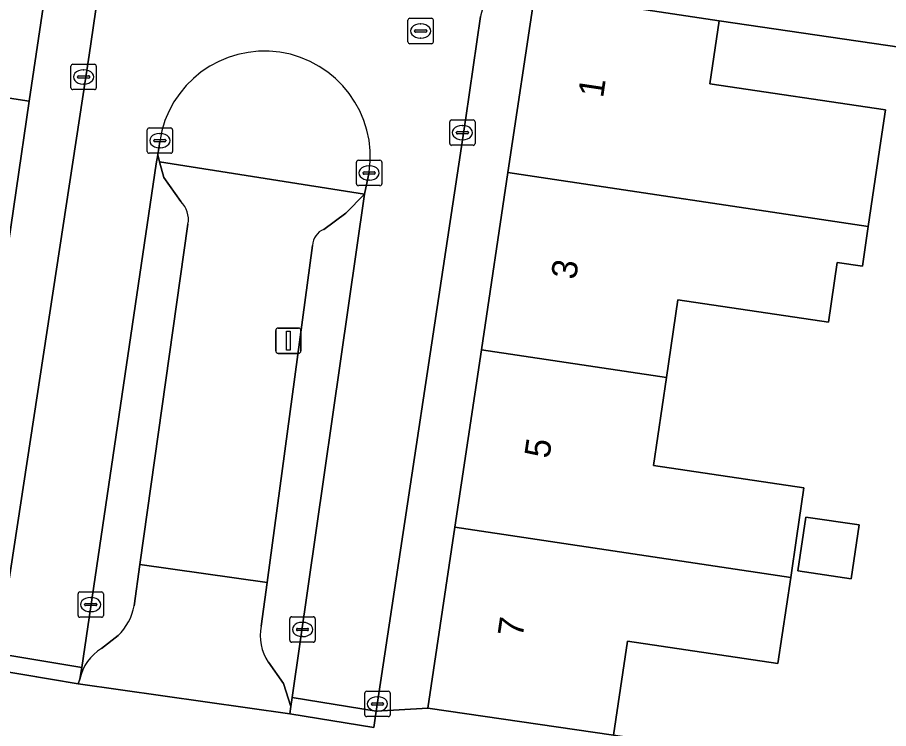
# Model space of a CAD drawing. Extents: x 163683 to 164494, y 382709 to 383872.
# Drawn here: x 164040.44 to 164074.8, y 383054.56 to 383082.57 of the extents above; entities that cross this region are included whole.
import ezdxf

# ---------------------------------------------------------------- set-up
doc = ezdxf.new("R2010")
doc.units = 0
for name, color, linetype in [('IMGEO_Erf', 7, 'Continuous'), ('IMGEO_Groenvoorziening', 7, 'Continuous'), ('IMGEO_Kolk', 7, 'Continuous'), ('IMGEO_Lichtmast', 7, 'Continuous'), ('IMGEO_Pand', 7, 'Continuous'), ('IMGEO_Pand_nummerreeks', 7, 'Continuous'), ('IMGEO_Parkeervlak_open', 7, 'Continuous'), ('IMGEO_Rijbaan_lokaal_open', 7, 'Continuous'), ('IMGEO_Rioolput', 7, 'Continuous'), ('IMGEO_Voetpad_open', 7, 'Continuous')]:
    doc.layers.add(name, color=color, linetype=linetype)

msp = doc.modelspace()

# ---------------------------------------------------------------- linework, layer by layer
at = {"layer": 'IMGEO_Erf'}
for points in [[(164079.081, 383080.842), (164068.118, 383082.441), (164067.751, 383079.962), (164074.676, 383078.936), (164074.495, 383077.716), (164073.995, 383074.34), (164073.762, 383072.77), (164072.773, 383072.917), (164072.426, 383070.573), (164066.489, 383071.452), (164066.035, 383068.386), (164065.522, 383064.923), (164071.458, 383064.044), (164071.165, 383062.066), (164070.935, 383060.513), (164070.432, 383057.12), (164064.496, 383057.999), (164063.947, 383054.299), (164074.971, 383052.645)], [(164073.633, 383062.582), (164073.319, 383060.464), (164071.222, 383060.775), (164071.536, 383062.892)]]:
    msp.add_lwpolyline(points, close=True, dxfattribs=at)
at = {"layer": 'IMGEO_Groenvoorziening'}
for points in [[(164046.054, 383077.691), (164045.976, 383077.163), (164046.049, 383076.883), (164054.125, 383075.618), (164054.32, 383076.482)], [(164052.524, 383074.226), (164053.388, 383074.861), (164054.125, 383075.618), (164046.049, 383076.883), (164046.212, 383076.262), (164046.887, 383075.323)], [(164047.17, 383074.431), (164045.275, 383061.028), (164050.291, 383060.313), (164052.079, 383073.592)], [(164050.06, 383058.594), (164050.291, 383060.313), (164045.275, 383061.028), (164045.045, 383059.399)], [(164044.412, 383058.222), (164043.757, 383057.707)], [(164042.911, 383056.507), (164042.84, 383056.324), (164051.188, 383055.135), (164051.231, 383055.427), (164050.934, 383056.333), (164050.338, 383057.172)]]:
    msp.add_lwpolyline(points, dxfattribs=at)
for centre, radius, start, end in [((164050.185, 383077.072), 4.177, 351.8809, 171.4767), ((164046.184, 383074.609), 1.002, 349.7759, 45.4289), ((164052.784, 383073.57), 0.705, 111.6311, 178.2395), ((164042.941, 383059.772), 2.137, 313.5087, 349.9478), ((164051.895, 383058.215), 1.874, 168.3167, 213.8069), ((164044.665, 383056.169), 1.786, 120.5437, 169.0887)]:
    msp.add_arc(centre, radius, start, end, dxfattribs=at)
at = {"layer": 'IMGEO_Kolk'}
for p, q in [((164042.628, 383080.731), (164043.48, 383080.731)), ((164042.553, 383079.805), (164042.553, 383080.657)), ((164043.041, 383080.511), (164043.066, 383080.511)), ((164043.554, 383080.657), (164043.554, 383079.805)), ((164042.812, 383080.225), (164042.812, 383080.237)), ((164043.25, 383080.188), (164042.852, 383080.188)), ((164042.855, 383080.274), (164043.253, 383080.274)), ((164043.296, 383080.237), (164043.296, 383080.225)), ((164043.48, 383079.731), (164042.628, 383079.731)), ((164043.064, 383079.951), (164043.039, 383079.951)), ((164057.492, 383077.61), (164057.492, 383078.462)), ((164057.567, 383078.536), (164058.419, 383078.536)), ((164058.493, 383078.462), (164058.493, 383077.61)), ((164045.56, 383077.297), (164045.56, 383078.149)), ((164045.635, 383078.223), (164046.487, 383078.223)), ((164046.048, 383078.003), (164046.073, 383078.003)), ((164046.561, 383078.149), (164046.561, 383077.297)), ((164057.751, 383078.03), (164057.751, 383078.042)), ((164058.189, 383077.993), (164057.791, 383077.993)), ((164057.794, 383078.079), (164058.192, 383078.079)), ((164057.98, 383078.316), (164058.005, 383078.316)), ((164058.235, 383078.042), (164058.235, 383078.03)), ((164045.819, 383077.717), (164045.819, 383077.729)), ((164046.257, 383077.68), (164045.859, 383077.68)), ((164045.862, 383077.766), (164046.26, 383077.766)), ((164046.303, 383077.729), (164046.303, 383077.717)), ((164058.003, 383077.756), (164057.978, 383077.756)), ((164046.071, 383077.443), (164046.046, 383077.443)), ((164058.419, 383077.536), (164057.567, 383077.536)), ((164046.487, 383077.223), (164045.635, 383077.223)), ((164053.887, 383076.947), (164054.739, 383076.947)), ((164053.812, 383076.021), (164053.812, 383076.873)), ((164054.3, 383076.727), (164054.325, 383076.727)), ((164054.813, 383076.873), (164054.813, 383076.021)), ((164054.071, 383076.441), (164054.071, 383076.453)), ((164054.509, 383076.404), (164054.111, 383076.404)), ((164054.114, 383076.49), (164054.512, 383076.49)), ((164054.555, 383076.453), (164054.555, 383076.441)), ((164054.739, 383075.947), (164053.887, 383075.947)), ((164054.323, 383076.167), (164054.298, 383076.167)), ((164042.835, 383059.018), (164042.835, 383059.87)), ((164042.91, 383059.944), (164043.762, 383059.944)), ((164043.836, 383059.87), (164043.836, 383059.018)), ((164043.094, 383059.438), (164043.094, 383059.45)), ((164043.137, 383059.487), (164043.535, 383059.487)), ((164043.323, 383059.724), (164043.348, 383059.724)), ((164043.578, 383059.45), (164043.578, 383059.438)), ((164043.532, 383059.401), (164043.134, 383059.401)), ((164043.346, 383059.164), (164043.321, 383059.164)), ((164043.762, 383058.944), (164042.91, 383058.944)), ((164051.185, 383058.036), (164051.185, 383058.888)), ((164051.26, 383058.962), (164052.112, 383058.962)), ((164051.673, 383058.742), (164051.698, 383058.742)), ((164052.186, 383058.888), (164052.186, 383058.036)), ((164051.444, 383058.456), (164051.444, 383058.468)), ((164051.882, 383058.419), (164051.484, 383058.419)), ((164051.487, 383058.505), (164051.885, 383058.505)), ((164051.928, 383058.468), (164051.928, 383058.456)), ((164051.696, 383058.182), (164051.671, 383058.182)), ((164052.112, 383057.962), (164051.26, 383057.962)), ((164054.216, 383056.029), (164055.068, 383056.029)), ((164054.141, 383055.103), (164054.141, 383055.955)), ((164054.629, 383055.809), (164054.654, 383055.809)), ((164055.142, 383055.955), (164055.142, 383055.103)), ((164054.4, 383055.523), (164054.4, 383055.535)), ((164054.838, 383055.486), (164054.44, 383055.486)), ((164054.443, 383055.572), (164054.841, 383055.572)), ((164054.884, 383055.535), (164054.884, 383055.523)), ((164055.068, 383055.029), (164054.216, 383055.029)), ((164054.652, 383055.249), (164054.627, 383055.249))]:
    msp.add_line(p, q, dxfattribs=at)
for points in [[(164042.628, 383080.731), (164043.48, 383080.731)], [(164042.553, 383079.805), (164042.553, 383080.657)], [(164043.554, 383080.657), (164043.554, 383079.805)], [(164043.48, 383079.731), (164042.628, 383079.731)], [(164057.492, 383077.61), (164057.492, 383078.462)], [(164057.567, 383078.536), (164058.419, 383078.536)], [(164058.493, 383078.462), (164058.493, 383077.61)], [(164045.56, 383077.297), (164045.56, 383078.149)], [(164045.635, 383078.223), (164046.487, 383078.223)], [(164046.561, 383078.149), (164046.561, 383077.297)], [(164058.419, 383077.536), (164057.567, 383077.536)], [(164046.487, 383077.223), (164045.635, 383077.223)], [(164053.887, 383076.947), (164054.739, 383076.947)], [(164053.812, 383076.021), (164053.812, 383076.873)], [(164054.813, 383076.873), (164054.813, 383076.021)], [(164054.739, 383075.947), (164053.887, 383075.947)], [(164042.835, 383059.018), (164042.835, 383059.87)], [(164042.91, 383059.944), (164043.762, 383059.944)], [(164043.836, 383059.87), (164043.836, 383059.018)], [(164043.762, 383058.944), (164042.91, 383058.944)], [(164051.185, 383058.036), (164051.185, 383058.888)], [(164051.26, 383058.962), (164052.112, 383058.962)], [(164052.186, 383058.888), (164052.186, 383058.036)], [(164052.112, 383057.962), (164051.26, 383057.962)], [(164054.216, 383056.029), (164055.068, 383056.029)], [(164054.141, 383055.103), (164054.141, 383055.955)], [(164055.142, 383055.955), (164055.142, 383055.103)], [(164055.068, 383055.029), (164054.216, 383055.029)]]:
    msp.add_lwpolyline(points, dxfattribs=at)
for centre, radius, start, end in [((164042.63, 383080.655), 0.0765, 91.552, 178.448), ((164042.63, 383080.655), 0.0765, 91.552, 178.448), ((164043.478, 383080.655), 0.0765, 1.552, 88.448), ((164043.478, 383080.655), 0.0765, 1.552, 88.448), ((164042.852, 383080.234), 0.0403, 85.8775, 175.7526), ((164042.849, 383080.224), 0.0366, 178.938, 274.7102), ((164043.253, 383080.231), 0.043, 264.8664, 352.4533), ((164043.257, 383080.236), 0.0386, 1.7309, 96.639), ((164042.63, 383079.807), 0.0765, 181.552, 268.448), ((164042.63, 383079.807), 0.0765, 181.552, 268.448), ((164043.478, 383079.807), 0.0765, 271.552, 358.448), ((164043.478, 383079.807), 0.0765, 271.552, 358.448), ((164057.569, 383078.46), 0.0765, 91.552, 178.448), ((164057.569, 383078.46), 0.0765, 91.552, 178.448), ((164058.417, 383078.46), 0.0765, 1.552, 88.448), ((164058.417, 383078.46), 0.0765, 1.552, 88.448), ((164045.637, 383078.147), 0.0765, 91.552, 178.448), ((164045.637, 383078.147), 0.0765, 91.552, 178.448), ((164046.485, 383078.147), 0.0765, 1.552, 88.448), ((164046.485, 383078.147), 0.0765, 1.552, 88.448), ((164057.791, 383078.039), 0.0403, 85.8775, 175.7526), ((164057.788, 383078.029), 0.0366, 178.938, 274.7102), ((164058.192, 383078.036), 0.043, 264.8664, 352.4533), ((164058.196, 383078.041), 0.0386, 1.7309, 96.639), ((164045.859, 383077.726), 0.0403, 85.8775, 175.7526), ((164045.856, 383077.716), 0.0366, 178.938, 274.7102), ((164046.26, 383077.723), 0.043, 264.8664, 352.4533), ((164046.264, 383077.728), 0.0386, 1.7309, 96.639), ((164045.637, 383077.299), 0.0765, 181.552, 268.448), ((164045.637, 383077.299), 0.0765, 181.552, 268.448), ((164046.485, 383077.299), 0.0765, 271.552, 358.448), ((164046.485, 383077.299), 0.0765, 271.552, 358.448), ((164057.569, 383077.612), 0.0765, 181.552, 268.448), ((164057.569, 383077.612), 0.0765, 181.552, 268.448), ((164058.417, 383077.612), 0.0765, 271.552, 358.448), ((164058.417, 383077.612), 0.0765, 271.552, 358.448), ((164053.889, 383076.871), 0.0765, 91.552, 178.448), ((164053.889, 383076.871), 0.0765, 91.552, 178.448), ((164054.737, 383076.871), 0.0765, 1.552, 88.448), ((164054.737, 383076.871), 0.0765, 1.552, 88.448), ((164054.111, 383076.45), 0.0403, 85.8775, 175.7526), ((164054.108, 383076.44), 0.0366, 178.938, 274.7102), ((164054.512, 383076.447), 0.043, 264.8664, 352.4533), ((164054.516, 383076.452), 0.0386, 1.7309, 96.639), ((164053.889, 383076.023), 0.0765, 181.552, 268.448), ((164053.889, 383076.023), 0.0765, 181.552, 268.448), ((164054.737, 383076.023), 0.0765, 271.552, 358.448), ((164054.737, 383076.023), 0.0765, 271.552, 358.448), ((164042.912, 383059.868), 0.0765, 91.552, 178.448), ((164042.912, 383059.868), 0.0765, 91.552, 178.448), ((164043.76, 383059.868), 0.0765, 1.552, 88.448), ((164043.76, 383059.868), 0.0765, 1.552, 88.448), ((164043.134, 383059.447), 0.0403, 85.8775, 175.7526), ((164043.131, 383059.437), 0.0366, 178.938, 274.7102), ((164043.535, 383059.444), 0.043, 264.8664, 352.4533), ((164043.539, 383059.449), 0.0386, 1.7309, 96.639), ((164042.912, 383059.02), 0.0765, 181.552, 268.448), ((164042.912, 383059.02), 0.0765, 181.552, 268.448), ((164043.76, 383059.02), 0.0765, 271.552, 358.448), ((164043.76, 383059.02), 0.0765, 271.552, 358.448), ((164051.262, 383058.886), 0.0765, 91.552, 178.448), ((164051.262, 383058.886), 0.0765, 91.552, 178.448), ((164052.11, 383058.886), 0.0765, 1.552, 88.448), ((164052.11, 383058.886), 0.0765, 1.552, 88.448), ((164051.484, 383058.465), 0.0403, 85.8775, 175.7526), ((164051.481, 383058.455), 0.0366, 178.938, 274.7102), ((164051.885, 383058.462), 0.043, 264.8664, 352.4533), ((164051.889, 383058.467), 0.0386, 1.7309, 96.639), ((164051.262, 383058.038), 0.0765, 181.552, 268.448), ((164051.262, 383058.038), 0.0765, 181.552, 268.448), ((164052.11, 383058.038), 0.0765, 271.552, 358.448), ((164052.11, 383058.038), 0.0765, 271.552, 358.448), ((164054.218, 383055.953), 0.0765, 91.552, 178.448), ((164054.218, 383055.953), 0.0765, 91.552, 178.448), ((164055.066, 383055.953), 0.0765, 1.552, 88.448), ((164055.066, 383055.953), 0.0765, 1.552, 88.448), ((164054.44, 383055.532), 0.0403, 85.8775, 175.7526), ((164054.437, 383055.522), 0.0366, 178.938, 274.7102), ((164054.841, 383055.529), 0.043, 264.8664, 352.4533), ((164054.845, 383055.534), 0.0386, 1.7309, 96.639), ((164054.218, 383055.105), 0.0765, 181.552, 268.448), ((164054.218, 383055.105), 0.0765, 181.552, 268.448), ((164055.066, 383055.105), 0.0765, 271.552, 358.448), ((164055.066, 383055.105), 0.0765, 271.552, 358.448)]:
    msp.add_arc(centre, radius, start, end, dxfattribs=at)
for centre, major_axis, ratio, start_param, end_param in [((164043.04, 383080.231), (-0.387, 0.002), 0.722429, 4.712389, 7.853982), ((164043.065, 383080.231), (-0.39, 0.002), 0.717154, 1.570796, 4.712389), ((164046.047, 383077.723), (-0.387, 0.002), 0.722429, 4.712389, 7.853982), ((164046.072, 383077.723), (-0.39, 0.002), 0.717154, 1.570796, 4.712389), ((164057.979, 383078.036), (-0.387, 0.002), 0.722429, 4.712389, 7.853982), ((164058.004, 383078.036), (-0.39, 0.002), 0.717154, 1.570796, 4.712389), ((164054.299, 383076.447), (-0.387, 0.002), 0.722429, 4.712389, 7.853982), ((164054.324, 383076.447), (-0.39, 0.002), 0.717154, 1.570796, 4.712389), ((164043.322, 383059.444), (-0.387, 0.002), 0.722429, 4.712389, 7.853982), ((164043.347, 383059.444), (-0.39, 0.002), 0.717154, 1.570796, 4.712389), ((164051.672, 383058.462), (-0.387, 0.002), 0.722429, 4.712389, 7.853982), ((164051.697, 383058.462), (-0.39, 0.002), 0.717154, 1.570796, 4.712389), ((164054.628, 383055.529), (-0.387, 0.002), 0.722429, 4.712389, 7.853982), ((164054.653, 383055.529), (-0.39, 0.002), 0.717154, 1.570796, 4.712389)]:
    msp.add_ellipse(centre, major_axis=major_axis, ratio=ratio, start_param=start_param, end_param=end_param, dxfattribs=at)
at = {"layer": 'IMGEO_Lichtmast'}
for p, q in [((164050.632, 383069.439), (164050.632, 383070.239)), ((164050.632, 383070.239), (164050.632, 383069.439)), ((164050.732, 383070.339), (164051.522, 383070.339)), ((164051.522, 383070.339), (164050.732, 383070.339)), ((164051.622, 383070.239), (164051.622, 383069.439)), ((164051.622, 383069.439), (164051.622, 383070.239)), ((164051.522, 383069.339), (164050.732, 383069.339)), ((164050.732, 383069.339), (164051.522, 383069.339))]:
    msp.add_line(p, q, dxfattribs=at)
msp.add_lwpolyline([(164051.052, 383070.214), (164051.202, 383070.214), (164051.202, 383069.464), (164051.052, 383069.464), (164051.052, 383070.214)], dxfattribs=at)
for centre, start, end in [((164050.732, 383070.239), 90, 180), ((164050.732, 383070.239), 90, 180), ((164051.522, 383070.239), 0, 90), ((164051.522, 383070.239), 360, 90), ((164050.732, 383069.439), 180, 270), ((164050.732, 383069.439), 180, 270), ((164051.522, 383069.439), 270, 0), ((164051.522, 383069.439), 270, 0)]:
    msp.add_arc(centre, 0.1, start, end, dxfattribs=at)
at = {"layer": 'IMGEO_Pand'}
for points in [[(164041.955, 383086.344), (164034.621, 383087.436), (164034.07, 383083.737), (164028.136, 383084.621), (164027.913, 383083.122), (164025.045, 383083.549), (164024.777, 383081.738), (164027.643, 383081.312), (164040.913, 383079.27)], [(164068.118, 383082.441), (164060.842, 383083.547), (164059.784, 383076.46), (164073.995, 383074.34), (164074.495, 383077.716), (164074.676, 383078.936), (164067.751, 383079.962)], [(164040.913, 383079.27), (164027.643, 383081.312), (164027.209, 383078.398), (164027.111, 383077.737), (164033.045, 383076.853), (164032.527, 383073.373), (164039.878, 383072.242)], [(164059.784, 383076.46), (164058.741, 383069.474), (164066.035, 383068.386), (164066.489, 383071.452), (164072.426, 383070.573), (164072.773, 383072.917), (164073.762, 383072.77), (164073.995, 383074.34)], [(164058.741, 383069.474), (164057.698, 383062.488), (164070.935, 383060.513), (164071.165, 383062.066), (164071.458, 383064.044), (164065.522, 383064.923), (164066.035, 383068.386)], [(164073.633, 383062.582), (164071.536, 383062.892), (164071.222, 383060.775), (164073.319, 383060.464)], [(164070.935, 383060.513), (164057.698, 383062.488), (164056.633, 383055.356), (164063.947, 383054.299), (164064.496, 383057.999), (164070.432, 383057.12)]]:
    msp.add_lwpolyline(points, close=True, dxfattribs=at)
at = {"layer": 'IMGEO_Parkeervlak_open'}
for points in [[(164046.887, 383075.323), (164046.212, 383076.262), (164046.049, 383076.883), (164045.976, 383077.163), (164045.921, 383076.806), (164042.978, 383056.96), (164042.911, 383056.507)], [(164050.338, 383057.172), (164050.934, 383056.333), (164051.231, 383055.427), (164051.281, 383055.779), (164054.125, 383075.618), (164053.388, 383074.861), (164052.524, 383074.226)], [(164045.045, 383059.399), (164045.275, 383061.028), (164047.17, 383074.431)], [(164052.079, 383073.592), (164050.291, 383060.313), (164050.06, 383058.594)], [(164043.757, 383057.707), (164044.412, 383058.222)]]:
    msp.add_lwpolyline(points, dxfattribs=at)
for centre, radius, start, end in [((164046.184, 383074.609), 1.002, 349.7759, 45.4289), ((164052.784, 383073.57), 0.705, 111.6311, 178.2395), ((164042.941, 383059.772), 2.137, 313.5087, 349.9478), ((164051.895, 383058.215), 1.874, 168.3167, 213.8069), ((164044.665, 383056.169), 1.786, 120.5437, 169.0887)]:
    msp.add_arc(centre, radius, start, end, dxfattribs=at)
at = {"layer": 'IMGEO_Rijbaan_lokaal_open'}
for points in [[(164043.851, 383085.289), (164043.854, 383085.06), (164043.271, 383081.092), (164039.653, 383057.519), (164042.978, 383056.96), (164045.921, 383076.806), (164045.976, 383077.163), (164046.054, 383077.691)], [(164054.32, 383076.482), (164054.125, 383075.618), (164051.281, 383055.779), (164054.596, 383055.242), (164058.121, 383078.624), (164058.702, 383082.608)]]:
    msp.add_lwpolyline(points, dxfattribs=at)
for points in [[(164042.84, 383056.324), (164042.911, 383056.507), (164042.978, 383056.96), (164039.653, 383057.519), (164039.556, 383056.876)], [(164054.596, 383055.242), (164051.281, 383055.779), (164051.231, 383055.427), (164051.188, 383055.135), (164054.5, 383054.599)]]:
    msp.add_lwpolyline(points, close=True, dxfattribs=at)
msp.add_arc((164050.185, 383077.072), 4.177, 351.8809, 171.4767, dxfattribs=at)
at = {"layer": 'IMGEO_Rioolput'}
for p, q in [((164055.843, 383081.614), (164055.843, 383082.466)), ((164055.918, 383082.54), (164056.77, 383082.54)), ((164056.844, 383082.466), (164056.844, 383081.614)), ((164056.331, 383082.32), (164056.356, 383082.32)), ((164056.102, 383082.034), (164056.102, 383082.046)), ((164056.54, 383081.997), (164056.142, 383081.997)), ((164056.145, 383082.083), (164056.543, 383082.083)), ((164056.354, 383081.76), (164056.329, 383081.76)), ((164056.586, 383082.046), (164056.586, 383082.034)), ((164056.77, 383081.54), (164055.918, 383081.54))]:
    msp.add_line(p, q, dxfattribs=at)
for points in [[(164055.843, 383081.614), (164055.843, 383082.466)], [(164055.918, 383082.54), (164056.77, 383082.54)], [(164056.844, 383082.466), (164056.844, 383081.614)], [(164056.77, 383081.54), (164055.918, 383081.54)]]:
    msp.add_lwpolyline(points, dxfattribs=at)
for centre, radius, start, end in [((164055.92, 383082.464), 0.0765, 91.552, 178.448), ((164055.92, 383082.464), 0.0765, 91.552, 178.448), ((164056.768, 383082.464), 0.0765, 1.552, 88.448), ((164056.768, 383082.464), 0.0765, 1.552, 88.448), ((164056.142, 383082.043), 0.0403, 85.8775, 175.7526), ((164056.139, 383082.033), 0.0366, 178.938, 274.7102), ((164056.543, 383082.04), 0.043, 264.8664, 352.4533), ((164056.547, 383082.045), 0.0386, 1.7309, 96.639), ((164055.92, 383081.616), 0.0765, 181.552, 268.448), ((164055.92, 383081.616), 0.0765, 181.552, 268.448), ((164056.768, 383081.616), 0.0765, 271.552, 358.448), ((164056.768, 383081.616), 0.0765, 271.552, 358.448)]:
    msp.add_arc(centre, radius, start, end, dxfattribs=at)
for centre, major_axis, ratio, start_param, end_param in [((164056.33, 383082.04), (-0.387, 0.002), 0.722429, 4.712389, 7.853982), ((164056.355, 383082.04), (-0.39, 0.002), 0.717154, 1.570796, 4.712389)]:
    msp.add_ellipse(centre, major_axis=major_axis, ratio=ratio, start_param=start_param, end_param=end_param, dxfattribs=at)
at = {"layer": 'IMGEO_Voetpad_open'}
for points in [[(164043.271, 383081.092), (164043.854, 383085.06), (164043.851, 383085.289), (164043.843, 383085.984), (164041.955, 383086.344), (164040.913, 383079.27), (164039.878, 383072.242), (164038.851, 383065.265), (164037.802, 383058.142), (164039.653, 383057.519)], [(164059.784, 383076.46), (164060.842, 383083.547), (164058.992, 383083.665), (164058.921, 383083.408), (164058.72, 383082.673), (164058.702, 383082.608), (164058.121, 383078.624), (164054.596, 383055.242), (164056.633, 383055.356), (164057.698, 383062.488), (164058.741, 383069.474)]]:
    msp.add_lwpolyline(points, close=True, dxfattribs=at)
for points in [[(164077.551, 383082.956), (164060.473, 383085.465), (164059.298, 383085.638), (164058.992, 383083.665), (164060.842, 383083.547), (164068.118, 383082.441), (164079.081, 383080.842), (164079.214, 383080.823), (164081.08, 383080.551), (164092.361, 383078.907), (164099.657, 383077.832), (164101.537, 383076.808)], [(164056.633, 383055.356), (164054.596, 383055.242), (164054.5, 383054.599), (164051.188, 383055.135), (164042.84, 383056.324), (164039.556, 383056.876), (164039.653, 383057.519), (164037.802, 383058.142), (164030.426, 383059.273), (164020.223, 383060.805), (164018.747, 383061.027), (164008.789, 383062.521), (164001.464, 383063.621), (163999.41, 383063.224), (163999.316, 383062.59), (163995.848, 383063.119), (163990.75, 383063.896), (163988.526, 383062.149), (163985.466, 383059.738)], [(164092.664, 383047.053), (164093.971, 383045.635), (164095.56, 383045.394), (164095.634, 383045.886), (164102.384, 383044.857), (164102.311, 383044.368), (164104.492, 383044.036), (164104.627, 383047.219), (164100.461, 383047.857), (164097.169, 383048.316), (164097.263, 383048.949), (164095.443, 383049.608), (164088.193, 383050.661), (164085.419, 383051.064), (164085.421, 383051.077), (164076.851, 383052.363), (164074.971, 383052.645), (164063.947, 383054.299), (164056.633, 383055.356)]]:
    msp.add_lwpolyline(points, dxfattribs=at)

# ---------------------------------------------------------------- texts
at = {"layer": 'IMGEO_Pand_nummerreeks'}
for s, rotation, p in [('1', 81.509, (164063.536, 383079.379)), ('3', 81.5083, (164062.467, 383072.218)), ('5', 81.5083, (164061.415, 383065.17)), ('7', 81.5083, (164060.362, 383058.123))]:
    msp.add_text(s, height=1, rotation=rotation, dxfattribs=at).set_placement(p)

doc.saveas('drawing.dxf')
